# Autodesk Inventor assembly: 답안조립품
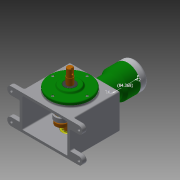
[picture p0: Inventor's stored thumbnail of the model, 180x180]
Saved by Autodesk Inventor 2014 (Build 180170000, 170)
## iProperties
Created: 2016-11
Part Number: 답안조립품
Document SubType Name: Assembly
Designer: NET
Mass: 3894.29 g
Surface Area: 4291.9 cm^2
Volume: 1585.28 cm^3
Density: 2.45653 g/cm^3
Author: NET
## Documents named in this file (16)
- C:\Users\NET\Desktop\361107V1007\답안조립품.iam
- C:\Users\NET\Desktop\361107V1007\본체.ipt
- C:\Users\NET\Desktop\361107V1007\가변스프링.ipt
- C:\Users\NET\Desktop\361107V1007\메인크랭크축.ipt
- C:\Users\NET\Desktop\361107V1007\베어링 20 x 47 x 14.ipt
- C:\Users\NET\Desktop\361107V1007\베어링 NA 4902.ipt
- C:\Users\NET\Desktop\361107V1007\볼트 M4 x 8.ipt
- C:\Users\NET\Desktop\361107V1007\볼트 M5 x 20.ipt
- C:\Users\NET\Desktop\361107V1007\실린더.ipt
- C:\Users\NET\Desktop\361107V1007\실린더헤드.ipt
- C:\Users\NET\Desktop\361107V1007\앞커버.ipt
- C:\Users\NET\Desktop\361107V1007\오일 실 20 35 8.ipt
- C:\Users\NET\Desktop\361107V1007\커넥팅로드.ipt
- C:\Users\NET\Desktop\361107V1007\크랭크보조축.ipt
- C:\Users\NET\Desktop\361107V1007\피스톤.ipt
- C:\Users\NET\Desktop\361107V1007\피스톤핀.ipt
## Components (15 placed, 5 different names)
1. 피스톤:1
2. 피스톤핀:1
3. 가변스프링:1
4. ISO 4762 M4 x 8:1
5. ISO 4762 M4 x 8:2
6. ISO 4762 M4 x 8:3
7. ISO 4762 M4 x 8:4
8. ISO 4762 M4 x 8:5
9. ISO 4762 M4 x 8:6
10. ISO 4762 M4 x 8:7
11. ISO 4762 M4 x 8:8
12. ISO 4762 M5 x 20:1
13. ISO 4762 M5 x 20:2
14. ISO 4762 M5 x 20:3
15. ISO 4762 M5 x 20:4
